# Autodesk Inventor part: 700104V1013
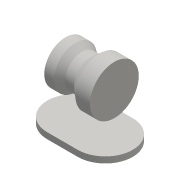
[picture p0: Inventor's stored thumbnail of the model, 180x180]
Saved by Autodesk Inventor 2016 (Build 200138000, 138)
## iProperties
Created: 2020-01
Part Number: 700104V1013
Material: Generic
Document SubType Name: Modeling
Designer: woori
Density: 1 g/cm^3
Appearance: Default
Author: woori
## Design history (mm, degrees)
sketch "스케치1"
  geometry: L1 (-25, 0)-(25, 0); L2 (-25, -45)-(25, -45); L3 (25, 45)-(-25, 45); A1 r 45 centre (-25, 0) between (-25, 45) and (-25, -45); A2 r 45 centre (25, 0) between (25, -45) and (25, 45); 2 further points
  constraints: 8 end point, 4 point on circle, 4 tangent, 2 centre point, 1 coincident, 1 horizontal, 1 midpoint, 1 parallel
  dimensions: "d0" = 50 distance of L3.start L3.end; "d1" = 45 radius of A1
extrude "돌출1" new body sketch "스케치1" distance "d2" = 10; taper "d3" = 0 deg
sketch "스케치2"
  geometry: L1 (0, 80)-(0, 0); L2 (0, 80)-(40, 80); L3 (40, 80)-(40, 115); L4 (40, 115)-(24, 115); L5 (24, 115)-(13.289, 107.5); L6 (13.289, 107.5)-(-1.103, 107.5); L7 (-1.103, 107.5)-(-16, 120); L8 (-16, 120)-(-40, 120); L9 (-40, 120)-(-40, 80); L10 (-40, 80)-(0, 80); L11 (-25, 0)-(-70, 0) reference; L12 (-70, 0)-(-70, 19.736)
  constraints: 22 end point, 4 perpendicular, 2 parallel, 2 vertical, 1 horizontal, 1 point on line
  dimensions: "d4" = 80 distance of L1.start L1.end; "d5" = 35 deg angle of L6 L5; "d6" = 40 deg angle of L6 L7; "d7" = 16 distance of L3.end L4.end; "d8" = 24 distance of L7.end L8.end; "d9" = 80 distance between parallel lines of L3 L9; "d10" = 55 diameter of L6 L10; "d11" = 80 diameter of L8 L10; "d12" = 70 diameter of L4 L2; "d13" = 30 distance between parallel lines of L12 L9
sketch "스케치3"
  geometry: L1 (-25, -45)-(25, -45) reference; L2 (25, 45)-(-25, 45) reference; L3 (0, 0)-(70, 0); A1 r 45 centre (25, 0) between (25, -45) and (25, 45) reference; A2 r 45 centre (-25, 0) between (-25, 45) and (-25, -45) reference
  constraints: 2 end point, 1 point on circle
revolve "회전1" stored, may be unused: angle "d14" = 90 deg
node "솔리드1"
